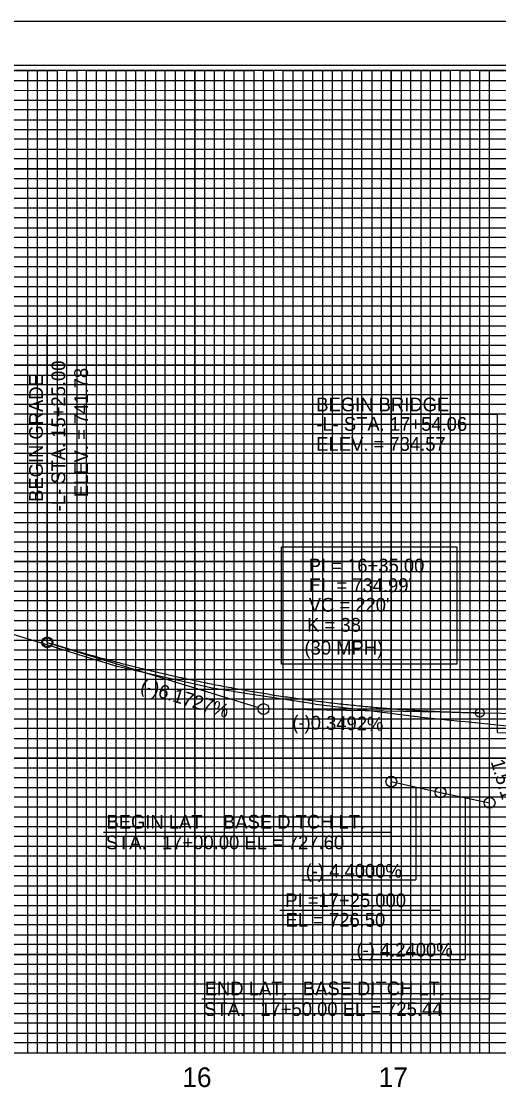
# Model space of a CAD drawing. Extents: x 573926 to 575610, y -51565 to -50465.
# Drawn here: x 574555 to 574797, y -51011 to -50465 of the extents above; entities that cross this region are included whole.
import ezdxf

# ---------------------------------------------------------------- set-up
doc = ezdxf.new("R2010")
doc.units = 0
for name, color, linetype in [('Default', 7, 'Continuous'), ('Exist Vertical Profile Horizontal Axis Label Major', 7, 'Continuous'), ('Old_Level_1', 7, 'Continuous'), ('Prop Dimension', 7, 'Continuous'), ('Prop Dimension Text', 7, 'Continuous'), ('Prop Grid Mask', 7, 'Continuous'), ('Prop Roadway Bridge', 7, 'Continuous'), ('Prop Vertical Profile Curve Label', 7, 'Continuous'), ('Prop Vertical Profile Ditch Grade Left', 7, 'Continuous'), ('Prop Vertical Profile Ditch Grade Left Label', 7, 'Continuous'), ('Prop Vertical Profile Grade', 7, 'Continuous'), ('Prop Vertical Profile Grade Label', 7, 'Continuous'), ('Prop VPI Ditch Grade Left Label', 7, 'Continuous'), ('Prop VPI Label', 7, 'Continuous'), ('Sheet Cutting Line CELL', 7, 'Continuous'), ('Sheet DOT Grid CELL', 7, 'Continuous'), ('Sheet Layout Profile Border Port 1', 7, 'Continuous'), ('Sheet Plot Border Inside CELL', 7, 'Continuous'), ('Sheet Plot Border Outside CELL', 7, 'Continuous'), ('Sheet Profile CELL', 7, 'Continuous'), ('Sheet Profile Grid Major CELL', 7, 'Continuous'), ('Sheet Profile Grid Middle CELL', 7, 'Continuous'), ('Sheet Profile Grid Minor CELL', 7, 'Continuous')]:
    doc.layers.add(name, color=color, linetype=linetype)

msp = doc.modelspace()

# ---------------------------------------------------------------- linework, layer by layer
at = {"layer": 'Default'}
msp.add_lwpolyline([(574549.29, -50776.61), (574578.4, -50785.6), (574579.22, -50785.86), (574601.51, -50792.74), (574601.84, -50792.82), (574631.48, -50799.56), (574632.24, -50799.73), (574653.12, -50804.47), (574653.89, -50804.62), (574672.8, -50807.55), (574675.13, -50807.91), (574702.09, -50812.08), (574704.42, -50812.44), (574725.57, -50815.06), (574728.72, -50815.44), (574755.76, -50818.79), (574758.06, -50819.06), (574777.79, -50821.12), (574780.55, -50821.4), (574807.9, -50824.25)], dxfattribs=at)
at = {"layer": 'Prop Dimension'}
for p, q in [((574567.78, -50781.05), (574567.78, -50624.01)), ((574701.84, -50664.95), (574796.84, -50664.95)), ((574796.84, -50817.08), (574796.84, -50664.95))]:
    msp.add_line(p, q, dxfattribs=at)
at = {"layer": 'Prop Grid Mask'}
msp.add_lwpolyline([(574686.89, -50732.42), (574776.12, -50732.42), (574776.12, -50792.12), (574686.89, -50792.12)], close=True, dxfattribs=at)
at = {"layer": 'Prop Roadway Bridge'}
for q in [(574796.84, -50817.08), (574905.11, -50828.76)]:
    msp.add_line((574796.84, -50826.87), q, dxfattribs=at)
at = {"layer": 'Prop Vertical Profile Curve Label'}
for centre in [(574567.78, -50781.05), (574787.78, -50816.92)]:
    msp.add_circle(centre, 2.25, dxfattribs=at)
at = {"layer": 'Prop Vertical Profile Ditch Grade Left'}
msp.add_lwpolyline([(574742.78, -50851.95), (574767.78, -50857.45), (574792.78, -50862.75)], dxfattribs=at)
at = {"layer": 'Prop Vertical Profile Grade'}
msp.add_line((574787.78, -50816.92), (574917.78, -50819.19), dxfattribs=at)
msp.add_spline([(574567.78, -50781.05), (574572.18, -50782.39), (574576.58, -50783.71), (574580.98, -50785), (574585.38, -50786.27), (574589.78, -50787.52), (574594.18, -50788.73), (574598.58, -50789.92), (574602.98, -50791.09), (574607.38, -50792.23), (574611.78, -50793.35), (574616.18, -50794.43), (574620.58, -50795.5), (574624.98, -50796.54), (574629.38, -50797.55), (574633.78, -50798.53), (574638.18, -50799.49), (574642.58, -50800.43), (574646.98, -50801.34), (574651.38, -50802.22), (574655.78, -50803.08), (574660.18, -50803.91), (574664.58, -50804.72), (574668.98, -50805.5), (574673.38, -50806.26), (574677.78, -50806.99), (574682.18, -50807.69), (574686.58, -50808.37), (574690.98, -50809.03), (574695.38, -50809.65), (574699.78, -50810.26), (574704.18, -50810.83), (574708.58, -50811.38), (574712.98, -50811.91), (574717.38, -50812.41), (574721.78, -50812.88), (574726.18, -50813.33), (574730.58, -50813.75), (574734.98, -50814.15), (574739.38, -50814.52), (574743.78, -50814.87), (574748.18, -50815.19), (574752.58, -50815.48), (574756.98, -50815.75), (574761.38, -50815.99), (574765.78, -50816.21), (574770.18, -50816.4), (574774.58, -50816.57), (574778.98, -50816.71), (574783.38, -50816.83), (574787.78, -50816.92)], degree=3, dxfattribs=at)
at = {"layer": 'Prop VPI Ditch Grade Left Label'}
for p, q in [((574742.78, -50877.7), (574742.78, -50854.7)), ((574755.28, -50854.7), (574755.28, -50902.02)), ((574767.78, -50860.2), (574767.78, -50917.46)), ((574780.28, -50860.1), (574780.28, -50942.5)), ((574792.78, -50865.5), (574792.78, -50962.55)), ((574596.41, -50877.7), (574742.78, -50877.7)), ((574697.23, -50902.02), (574755.28, -50902.02)), ((574686.05, -50917.46), (574767.78, -50917.46)), ((574722.2, -50942.5), (574780.28, -50942.5)), ((574646.41, -50962.55), (574792.78, -50962.55))]:
    msp.add_line(p, q, dxfattribs=at)
for centre in [(574742.78, -50851.95), (574767.78, -50857.45), (574792.78, -50862.75)]:
    msp.add_circle(centre, 2.75, dxfattribs=at)
at = {"layer": 'Prop VPI Label'}
for p, q in [((574567.78, -50781.05), (574675.15, -50814.19)), ((574787.78, -50816.92), (574680.53, -50815.04))]:
    msp.add_line(p, q, dxfattribs=at)
for centre in [(574567.78, -50781.05), (574677.78, -50815)]:
    msp.add_circle(centre, 2.75, dxfattribs=at)
at = {"layer": 'Sheet Cutting Line CELL'}
msp.add_line((575609.78, -50464.95), (573925.78, -50464.95), dxfattribs=at)
at = {"layer": 'Sheet DOT Grid CELL'}
for p, q in [((574592.78, -50989.95), (574592.78, -50489.95)), ((574642.78, -50989.95), (574642.78, -50489.95)), ((574692.78, -50989.95), (574692.78, -50489.95)), ((574742.78, -50989.95), (574742.78, -50489.95)), ((574792.78, -50989.95), (574792.78, -50489.95)), ((575392.73, -50539.95), (574092.78, -50539.95)), ((575392.73, -50589.95), (574092.78, -50589.95)), ((575592.78, -50639.95), (574092.78, -50639.95)), ((575592.78, -50689.95), (574092.78, -50689.95)), ((575592.78, -50739.95), (574092.78, -50739.95)), ((575592.78, -50789.95), (574092.78, -50789.95)), ((575592.78, -50839.95), (574092.78, -50839.95)), ((575592.78, -50889.95), (574092.78, -50889.95)), ((575592.78, -50939.95), (574092.78, -50939.95))]:
    msp.add_line(p, q, dxfattribs=at)
at = {"layer": 'Sheet Layout Profile Border Port 1'}
msp.add_lwpolyline([(574142.78, -50489.95), (574142.78, -50989.95), (575542.78, -50989.95), (575542.78, -50627.5), (575392.73, -50627.5), (575392.73, -50489.95)], close=True, dxfattribs=at)
at = {"layer": 'Sheet Plot Border Inside CELL'}
msp.add_lwpolyline([(573938.78, -51542.5), (575605.28, -51542.5), (575605.28, -50487.4), (573938.78, -50487.4)], close=True, dxfattribs=at)
at = {"layer": 'Sheet Plot Border Outside CELL'}
msp.add_lwpolyline([(573925.78, -51564.95), (575609.78, -51564.95), (575609.78, -50464.95), (573925.78, -50464.95)], close=True, dxfattribs=at)
at = {"layer": 'Sheet Profile CELL'}
msp.add_line((574092.78, -50989.95), (575592.78, -50989.95), dxfattribs=at)
msp.add_lwpolyline([(575592.78, -50489.95), (574092.78, -50489.95), (574092.78, -51539.95), (575592.78, -51539.95)], close=True, dxfattribs=at)
at = {"layer": 'Sheet Profile Grid Major CELL'}
for points in [[(574542.78, -50989.95), (574592.78, -50989.95), (574592.78, -50489.95), (574642.78, -50489.95), (574642.78, -50989.95), (574692.78, -50989.95), (574692.78, -50489.95), (574742.78, -50489.95), (574742.78, -50989.95), (574792.78, -50989.95), (574792.78, -50489.95), (574842.78, -50489.95), (574842.78, -50989.95), (574892.78, -50989.95), (574892.78, -50489.95), (574942.78, -50489.95), (574942.78, -50989.95), (574992.78, -50989.95), (574992.78, -50489.95), (575042.78, -50489.95), (575042.78, -50989.95), (575092.78, -50989.95), (575092.78, -50489.95), (575142.78, -50489.95)], [(574092.78, -50539.95), (575392.78, -50539.95)], [(575392.78, -50589.95), (574092.78, -50589.95), (574092.78, -50639.95), (575592.78, -50639.95)], [(575592.78, -50689.95), (574092.78, -50689.95), (574092.78, -50739.95), (575592.78, -50739.95)], [(575592.78, -50789.95), (574092.78, -50789.95), (574092.78, -50839.95), (575592.78, -50839.95)], [(575592.78, -50889.95), (574092.78, -50889.95), (574092.78, -50889.95), (574092.78, -50939.95), (575592.78, -50939.95)]]:
    msp.add_lwpolyline(points, dxfattribs=at)
at = {"layer": 'Sheet Profile Grid Middle CELL'}
msp.add_line((574092.78, -50514.95), (575392.73, -50514.95), dxfattribs=at)
for points in [[(574517.78, -50489.95), (574567.78, -50489.95), (574567.78, -50989.95), (574617.78, -50989.95), (574617.78, -50489.95), (574667.78, -50489.95), (574667.78, -50989.95), (574717.78, -50989.95), (574717.78, -50989.95), (574717.78, -50489.95), (574767.78, -50489.95), (574767.78, -50989.95), (574817.78, -50989.95)], [(575392.78, -50564.95), (574092.78, -50564.95), (574092.78, -50614.95), (575392.78, -50614.95)], [(575592.78, -50664.95), (574092.78, -50664.95), (574092.78, -50714.95), (575417.78, -50714.95)], [(575592.78, -50764.95), (574092.78, -50764.95), (574092.78, -50814.95), (575592.78, -50814.95)], [(575592.78, -50864.95), (574092.78, -50864.95), (574092.78, -50914.95), (575592.78, -50914.95)], [(575592.78, -50964.95), (574092.78, -50964.95)]]:
    msp.add_lwpolyline(points, dxfattribs=at)
at = {"layer": 'Sheet Profile Grid Minor CELL'}
for p, q in [((574142.78, -50494.95), (575392.78, -50494.95)), ((575392.78, -50499.95), (574142.78, -50500.3)), ((574142.78, -50504.95), (575392.78, -50504.95)), ((575392.73, -50624.95), (574142.78, -50624.95)), ((575542.78, -50629.95), (574142.78, -50629.95)), ((575542.78, -50634.95), (574142.78, -50634.95)), ((574142.78, -50644.95), (575542.78, -50644.95)), ((575542.78, -50649.95), (574142.78, -50649.95)), ((574142.78, -50654.95), (575542.78, -50654.95)), ((575542.78, -50674.95), (574142.78, -50674.95)), ((574142.78, -50679.95), (575542.78, -50679.95)), ((575542.78, -50699.95), (574142.78, -50699.95)), ((574142.78, -50704.95), (575542.78, -50704.95)), ((575542.78, -50724.95), (574142.78, -50724.95)), ((574142.78, -50729.95), (575542.78, -50729.95)), ((575542.78, -50734.95), (574142.78, -50734.95)), ((574142.78, -50744.95), (575542.78, -50744.95)), ((575542.78, -50749.95), (574142.78, -50749.95)), ((574142.78, -50754.95), (575542.78, -50754.95)), ((575542.78, -50759.95), (574142.78, -50759.95)), ((574142.78, -50769.95), (575542.78, -50769.95)), ((575542.78, -50774.95), (574142.78, -50774.95)), ((574142.78, -50779.95), (575542.78, -50779.95)), ((575542.78, -50784.95), (574142.78, -50784.95)), ((574142.78, -50794.95), (575542.78, -50794.95)), ((575542.78, -50799.95), (574142.78, -50799.95)), ((574142.78, -50804.95), (575542.78, -50804.95)), ((575542.78, -50809.95), (574142.78, -50809.95)), ((574142.78, -50819.95), (575542.78, -50819.95)), ((575542.78, -50824.95), (574142.78, -50824.95)), ((574142.78, -50829.95), (575542.78, -50829.95)), ((575542.78, -50834.95), (574142.78, -50834.95)), ((574142.78, -50844.95), (575542.78, -50844.95)), ((575542.78, -50849.95), (574142.78, -50849.95)), ((574142.78, -50854.95), (575542.78, -50854.95)), ((575542.78, -50859.95), (574142.78, -50859.95)), ((574142.78, -50869.95), (575542.78, -50869.95)), ((575542.78, -50874.95), (574142.78, -50874.95)), ((575542.78, -50879.95), (574142.78, -50879.95)), ((575542.78, -50884.95), (574142.78, -50884.95)), ((574142.78, -50894.95), (575542.78, -50894.95)), ((575542.78, -50899.95), (574142.78, -50899.95)), ((574142.78, -50904.95), (575542.78, -50904.95)), ((575542.78, -50909.95), (574142.78, -50909.95)), ((574142.78, -50919.95), (575542.78, -50919.95)), ((575542.78, -50924.95), (574142.78, -50924.95)), ((574142.78, -50929.95), (575542.78, -50929.95)), ((575542.78, -50934.95), (574142.78, -50934.95)), ((574142.78, -50944.95), (575542.78, -50944.95)), ((575542.78, -50949.95), (574142.78, -50949.95)), ((574142.78, -50954.95), (575542.78, -50954.95)), ((575542.78, -50959.95), (574142.78, -50959.95)), ((574142.78, -50969.95), (575542.78, -50969.95)), ((575542.78, -50974.95), (574142.78, -50974.95)), ((574142.78, -50979.95), (575542.78, -50979.95))]:
    msp.add_line(p, q, dxfattribs=at)
for points in [[(574552.78, -50489.95), (574557.78, -50489.95), (574557.78, -50989.95), (574562.78, -50989.95), (574562.78, -50489.95), (574572.78, -50489.95), (574572.78, -50989.95), (574577.78, -50989.95), (574577.78, -50489.95), (574582.78, -50489.95), (574582.78, -50989.95), (574587.78, -50989.95), (574587.78, -50489.95), (574597.78, -50489.95), (574597.78, -50989.95), (574602.78, -50989.95), (574602.78, -50489.95), (574607.78, -50489.95), (574607.78, -50989.95), (574612.78, -50989.95), (574612.78, -50489.95), (574622.78, -50489.95), (574622.78, -50989.95), (574627.78, -50989.95), (574627.78, -50489.95), (574632.78, -50489.95), (574632.78, -50989.95), (574637.78, -50989.95), (574637.78, -50489.95), (574647.78, -50489.95), (574647.78, -50989.95), (574652.78, -50989.95), (574652.78, -50489.95), (574657.78, -50489.95), (574657.78, -50989.95), (574662.78, -50989.95), (574662.78, -50489.95), (574672.78, -50489.95)], [(574672.78, -50489.95), (574672.78, -50989.95), (574677.78, -50989.95), (574677.78, -50489.95), (574682.78, -50489.95), (574682.78, -50989.95), (574687.78, -50989.95), (574687.78, -50489.95), (574697.78, -50489.95), (574697.78, -50989.95), (574702.78, -50989.95), (574702.78, -50489.95), (574707.78, -50489.95), (574707.78, -50989.95), (574712.78, -50989.95), (574712.78, -50489.95), (574722.78, -50489.95), (574722.78, -50989.95), (574727.78, -50989.95), (574727.78, -50489.95), (574732.78, -50489.95), (574732.78, -50989.95), (574737.78, -50989.95), (574737.78, -50489.95), (574747.78, -50489.95), (574747.78, -50989.95), (574752.78, -50989.95), (574752.78, -50489.95), (574757.78, -50489.95), (574757.78, -50989.95), (574762.78, -50989.95), (574762.78, -50489.95), (574772.78, -50489.95), (574772.78, -50989.95), (574777.78, -50989.95), (574777.78, -50489.95), (574782.78, -50489.95), (574782.78, -50989.95), (574787.78, -50989.95), (574787.78, -50489.95), (574797.78, -50489.95)], [(575392.78, -50509.95), (574142.78, -50509.95), (574142.78, -50519.95), (575392.78, -50519.95)], [(575392.73, -50524.95), (574142.78, -50524.95), (574142.78, -50529.95), (575392.78, -50529.95)], [(575392.78, -50534.95), (574142.78, -50534.95), (574142.78, -50544.95), (575392.78, -50544.95)], [(575392.78, -50549.95), (574142.78, -50549.95), (574142.78, -50554.95), (575392.78, -50554.95)], [(575392.78, -50559.95), (574142.78, -50559.95), (574142.78, -50569.95), (575392.78, -50569.95)], [(575392.78, -50574.95), (574142.78, -50574.95), (574142.78, -50579.95), (575392.78, -50579.95)], [(575392.78, -50584.95), (574142.78, -50584.95), (574142.78, -50594.95), (575392.78, -50594.95)], [(575392.78, -50600.05), (574142.88, -50600.05), (574142.88, -50604.95), (575392.78, -50604.95)], [(575392.78, -50609.95), (574142.78, -50609.95), (574142.78, -50619.95), (575392.78, -50619.95)], [(575542.78, -50659.95), (574142.78, -50659.95), (574142.78, -50669.95), (575542.78, -50669.95)], [(575542.78, -50684.95), (574142.78, -50684.95), (574142.78, -50694.95), (575542.78, -50694.95)], [(575542.78, -50709.95), (574142.78, -50709.95), (574142.78, -50719.95), (575542.78, -50719.95)], [(575542.78, -50984.95), (574142.78, -50984.95)]]:
    msp.add_lwpolyline(points, dxfattribs=at)

# ---------------------------------------------------------------- texts
at = {"layer": 'Exist Vertical Profile Horizontal Axis Label Major'}
for s, p in [('16', (574636.46, -51007.45)), ('17', (574736.32, -51007.45))]:
    msp.add_text(s, height=10, dxfattribs=at).set_placement(p)
at = {"layer": 'Old_Level_1'}
msp.add_text('1.5:1', height=7, rotation=286.6992, dxfattribs=at).set_placement((574793.22, -50841.7))
at = {"layer": 'Prop Dimension Text'}
for s, rotation, p in [('-L- STA. 15+25.00', 90, (574576.89, -50714.34)), ('ELEV. = 741.78', 90, (574588.49, -50707.15)), ('BEGIN GRADE', 90, (574565.55, -50709.54)), ('BEGIN BRIDGE', 360, (574704.59, -50663.43)), ('-L- STA. 17+54.06', 360, (574704.59, -50673.35)), ('ELEV. = 734.57', 360, (574704.59, -50683.53))]:
    msp.add_text(s, height=7, rotation=rotation, dxfattribs=at).set_placement(p)
at = {"layer": 'Prop Vertical Profile Curve Label'}
for s, p in [("VC = 220'", (574700.76, -50765.45)), ('K = 38', (574699.97, -50775.63)), ('(30 MPH)', (574698.59, -50787.28))]:
    msp.add_text(s, height=7, dxfattribs=at).set_placement(p)
at = {"layer": 'Prop Vertical Profile Ditch Grade Left Label'}
for s, p in [('(-) 4.4000%', (574699.21, -50900.88)), ('(-) 4.2400%', (574725.03, -50941.07))]:
    msp.add_text(s, height=7, rotation=360, dxfattribs=at).set_placement(p)
at = {"layer": 'Prop Vertical Profile Grade Label'}
for s, rotation, p in [('(-)6.1727%', 342.8479, (574614.65, -50805.98)), ('(-)0.3492%', 358.9997, (574692.36, -50825.25))]:
    msp.add_text(s, height=7, rotation=rotation, dxfattribs=at).set_placement(p)
at = {"layer": 'Prop VPI Ditch Grade Left Label'}
for s, p in [('BEGIN LAT.   BASE DITCH LT.', (574597.85, -50875.9)), ('STA.   17+00.00 EL = 727.60', (574597.52, -50886.39)), ('PI =17+25.000', (574688.82, -50915.86)), ('EL = 726.50', (574688.96, -50925.84)), ('END LAT.   BASE DITCH LT.', (574647.85, -50960.75))]:
    msp.add_text(s, height=7, rotation=360, dxfattribs=at).set_placement(p)
msp.add_text('STA.   17+50.00 EL = 725.44', height=7, dxfattribs=at).set_placement((574647.52, -50971.24))
at = {"layer": 'Prop VPI Label'}
for s, p in [('PI = 16+35.00', (574700.76, -50745.45)), ("EL = 734.99'", (574700.76, -50755.45))]:
    msp.add_text(s, height=7, dxfattribs=at).set_placement(p)

doc.saveas('drawing.dxf')
